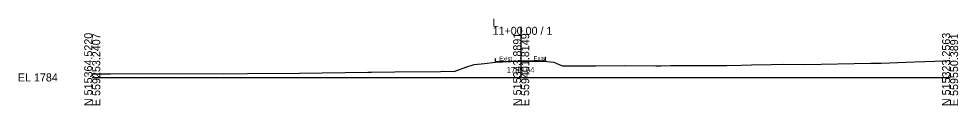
# Model space of a CAD drawing. Extents: x -26 to 1303, y -10 to 9545.
# Drawn here: x -25.7 to 302.8, y 1990.3 to 2020.5 of the extents above; entities that cross this region are included whole.
import ezdxf

# ---------------------------------------------------------------- set-up
doc = ezdxf.new("R2010")
doc.units = 0
for name, color, linetype in [('Exist Cross Section Cell', 7, 'Continuous'), ('Exist XS Center Line Elevation Label', 7, 'Continuous'), ('Exist XS Ground Line', 7, 'Continuous'), ('Prop XS EOT Tick Mark', 7, 'Continuous'), ('Prop XS Finish Grade Pavement', 7, 'Continuous'), ('Prop XS SE Text', 7, 'Continuous')]:
    doc.layers.add(name, color=color, linetype=linetype)

msp = doc.modelspace()

# ---------------------------------------------------------------- linework, layer by layer
at = {"layer": 'Exist Cross Section Cell'}
for p, q in [((150, 2000), (150, 2017.68)), ((0, 2000), (150, 2000)), ((150, 2000), (300, 2000))]:
    msp.add_line(p, q, dxfattribs=at)
at = {"layer": 'Exist XS Ground Line'}
for p, q in [((130.65, 2003.55), (133.61, 2004.53)), ((133.61, 2004.53), (137.13, 2004.92)), ((137.13, 2004.92), (140.98, 2005.36)), ((140.98, 2005.36), (146.29, 2005.52)), ((146.29, 2005.52), (149.76, 2005.64)), ((149.76, 2005.64), (154.86, 2005.61)), ((154.86, 2005.61), (157.98, 2005.64)), ((157.98, 2005.64), (159.09, 2005.51)), ((159.09, 2005.51), (161.43, 2005.3)), ((161.43, 2005.3), (163.5, 2004.39)), ((163.5, 2004.39), (164.41, 2004.02)), ((164.97, 2004.03), (168.61, 2004.08)), ((168.61, 2004.08), (171.39, 2004.03)), ((171.39, 2004.03), (176.14, 2004.11)), ((176.14, 2004.11), (186.07, 2004.13)), ((186.07, 2004.13), (197.12, 2004.04)), ((197.12, 2004.04), (198.8, 2004.07)), ((198.8, 2004.07), (202.31, 2004.12)), ((202.31, 2004.12), (206.06, 2004.16)), ((206.06, 2004.16), (213.96, 2004.12)), ((213.96, 2004.12), (221.97, 2004.14)), ((221.97, 2004.14), (227.04, 2004.24)), ((227.04, 2004.24), (230.53, 2004.39)), ((230.53, 2004.39), (237.57, 2004.51)), ((237.57, 2004.51), (241.59, 2004.66)), ((241.59, 2004.66), (249.14, 2004.56)), ((249.14, 2004.56), (272.28, 2004.97)), ((272.28, 2004.97), (274.36, 2005.01)), ((274.36, 2005.01), (275.93, 2005.03)), ((275.93, 2005.03), (287.54, 2005.41)), ((287.54, 2005.41), (298.27, 2005.8)), ((298.27, 2005.8), (299.64, 2005.86)), ((299.64, 2005.86), (300, 2005.89)), ((0, 2001.22), (6.34, 2001.29)), ((6.34, 2001.29), (16.08, 2001.36)), ((16.08, 2001.36), (21.87, 2001.25)), ((21.87, 2001.25), (31.14, 2001.4)), ((31.14, 2001.4), (46.02, 2001.2)), ((46.02, 2001.2), (54.31, 2001.42)), ((54.31, 2001.42), (72.45, 2001.53)), ((72.45, 2001.53), (96.42, 2001.8)), ((96.42, 2001.8), (97.68, 2001.8)), ((97.68, 2001.8), (105.85, 2001.92)), ((105.85, 2001.92), (121.79, 2002.13)), ((121.79, 2002.13), (122.38, 2002.15)), ((122.38, 2002.15), (126.6, 2002.09)), ((126.6, 2002.09), (130.65, 2003.55)), ((164.41, 2004.02), (164.97, 2004.03))]:
    msp.add_line(p, q, dxfattribs=at)
at = {"layer": 'Prop XS EOT Tick Mark'}
for p, q in [((140.99, 2005.56), (140.99, 2006.56)), ((158.45, 2005.91), (158.45, 2006.91))]:
    msp.add_line(p, q, dxfattribs=at)
at = {"layer": 'Prop XS Finish Grade Pavement'}
for p, q in [((140.99, 2005.56), (150, 2005.77)), ((150, 2005.77), (158.45, 2005.91))]:
    msp.add_line(p, q, dxfattribs=at)

# ---------------------------------------------------------------- texts
at = {"layer": 'Exist Cross Section Cell'}
for s, p in [('11+00.00 / 1', (140, 2014.88)), ('L', (140, 2017.68)), ('EL 1784', (-26, 1998.6))]:
    msp.add_text(s, height=2.8, dxfattribs=at).set_placement(p)
for s, p in [('N 515364.5220', (0, 1990)), ('E 559253.2407', (2.8, 1990)), ('N 515343.8891', (150, 1990)), ('E 559401.8149', (152.8, 1990)), ('N 515323.2563', (300, 1990)), ('E 559550.3891', (302.8, 1990))]:
    msp.add_text(s, height=2.8, rotation=90, dxfattribs=at).set_placement(p)
at = {"layer": 'Exist XS Center Line Elevation Label'}
msp.add_text('1789.64', height=2, dxfattribs=at).set_placement((144.98, 2001.64))
at = {"layer": 'Prop XS SE Text'}
for p in [(142.33, 2005.75), (154.36, 2005.94)]:
    msp.add_text('Exist', height=1.5, rotation=1.3214, dxfattribs=at).set_placement(p)

doc.saveas('drawing.dxf')
